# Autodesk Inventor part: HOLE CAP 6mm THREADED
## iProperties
Created: 2007-01
Part Number: HOLE CAP 6mm THREADED
Material: PVC-U
Document SubType Name: Modeling
Designer: Andy Moles
Density: 1.4 g/cm^3
Author: Andy Moles
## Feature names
1. Revolution1
